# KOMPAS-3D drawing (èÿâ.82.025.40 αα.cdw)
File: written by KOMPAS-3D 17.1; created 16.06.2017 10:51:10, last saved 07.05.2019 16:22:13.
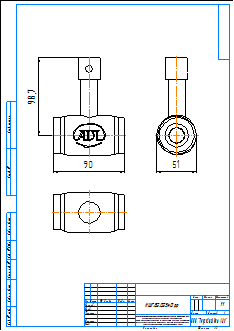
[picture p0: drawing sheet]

Sheet 1: A3, portrait

Title block, sheet 1: name: КШГ.82.025.40 рр; material: Внимание! Данный продукт является объектом авторского права ООО «Торговый Дом АДЛ». / Запрещается изменение, копирование, распространение / (в том числе путем копирования на другие сайты и ресурсы в Интернете) / или любое иное использование информации и объектов без предварительного / согласия правообладателя (ООО «Торговый Дом АДЛ»).; scale: 1:1; sheets: 1; organisation: ООО "Торговый дом АДЛ"; sheet format: A3; stored path: C:\Users\tra\Desktop\2д чертежи\Шаровые краны БИВАЛ\КШ_Бивал_серия_82_85\KOMPAS 2D\КШГ.82.025.40 рр.cdw

Views: Спереди 1, Проекционный вид 2, Проекционный вид 3
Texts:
  Klimkovich
  ADL
Dimensions and other numbers on the sheet: 90; 98,7; 51; 1:1; 1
